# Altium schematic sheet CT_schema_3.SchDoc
size 207 x 169 mm
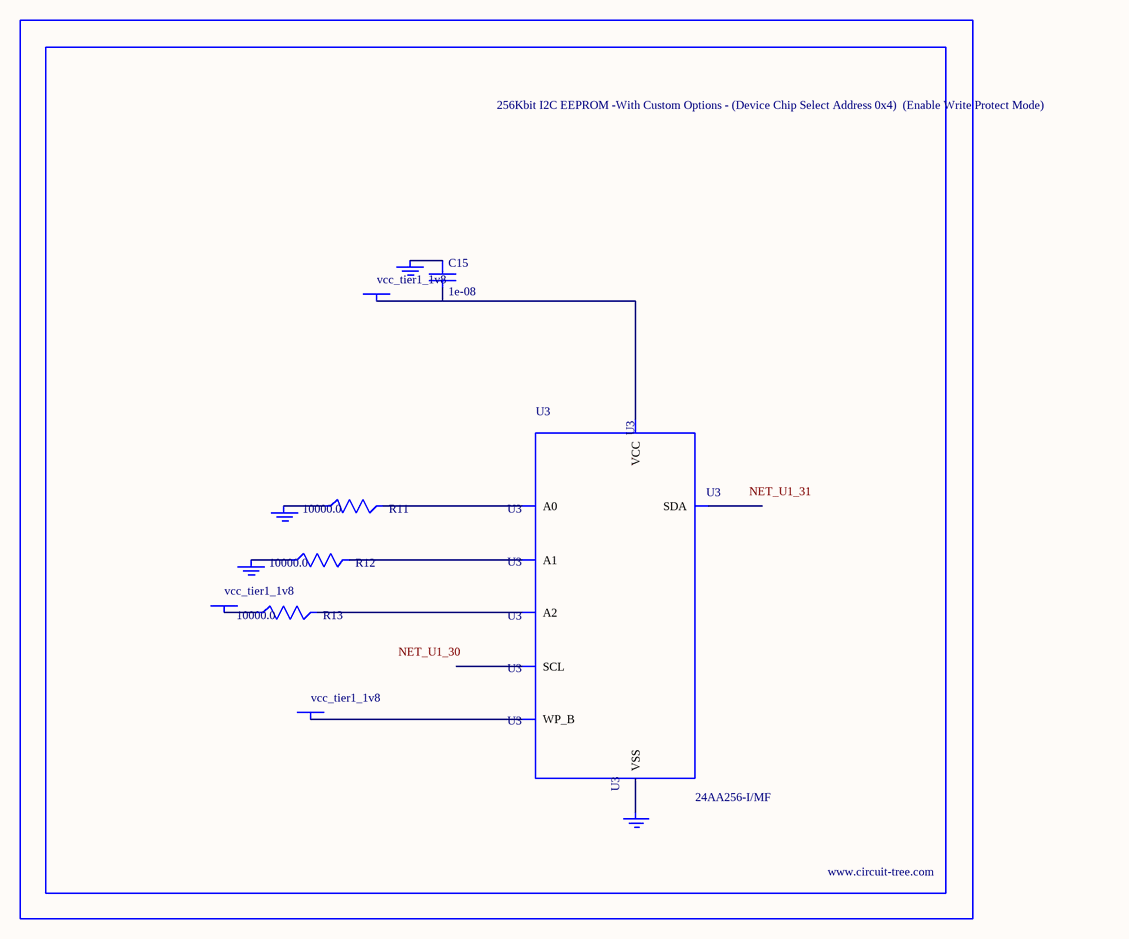
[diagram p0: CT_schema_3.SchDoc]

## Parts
BORDER2  (no value)
C15  1e-08  [C0402]
GND_INSTANCE_2_0  (no value)
GND_INSTANCE_2_1  (no value)
GND_INSTANCE_2_2  (no value)
GND_INSTANCE_2_3  (no value)
POWER_INSTANCE_2_0  vcc_tier1_1v8
POWER_INSTANCE_2_1  vcc_tier1_1v8
POWER_INSTANCE_2_2  vcc_tier1_1v8
R11  10000.0  [R0603]
R12  10000.0  [R0603]
R13  10000.0  [R0603]
U3  24AA256-I/MF  [DFN8-S]

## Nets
NetC15_1: C15.1 GND_INSTANCE_2_2.0(GND)
NetC15_2: C15.2 POWER_INSTANCE_2_2.0(PWR) U3.8(VCC)
NetGND_INSTANCE_2_0_0: GND_INSTANCE_2_0.0(GND) R11.1
NetGND_INSTANCE_2_1_0: GND_INSTANCE_2_1.0(GND) R12.1
NetGND_INSTANCE_2_3_0: GND_INSTANCE_2_3.0(GND) U3.4(VSS)
NetPOWER_INSTANCE_2_0_0: POWER_INSTANCE_2_0.0(PWR) R13.1
NetPOWER_INSTANCE_2_1_0: POWER_INSTANCE_2_1.0(PWR) U3.7(WP_B)
NetR11_2: R11.2 U3.1(A0)
NetR12_2: R12.2 U3.2(A1)
NetR13_2: R13.2 U3.3(A2)

Not connected (* = marked no-connect by the designer): U3 5(SDA) 6(SCL)

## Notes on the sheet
- Labels drawn without touching a wire or pin: NET_U1_30, NET_U1_31

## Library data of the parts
BORDER2 = BORDER_PAGE2
C15 = C0402C103K3RAC
GND_INSTANCE_2_0-GND_INSTANCE_2_3 = GND
POWER_INSTANCE_2_0-POWER_INSTANCE_2_2 = PWR
R11-R13 = RC0603JR-0710KL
